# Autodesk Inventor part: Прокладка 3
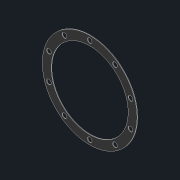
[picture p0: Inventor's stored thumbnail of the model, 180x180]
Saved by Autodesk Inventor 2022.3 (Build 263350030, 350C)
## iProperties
Created: 2022-08
Part Number: Прокладка 3
Material: Резина
Document SubType Name: Modeling
Designer: Карташов
Density: 0.93 g/cm^3
Appearance: Резина — черная
Author: Карташов
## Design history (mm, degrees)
sketch "Эскиз1"
  geometry: L1 (-320, -7.5)-(-320, 7.5) reference; L2 (-320, -7.5)-(-208, -7.5) reference; L3 (-68, -7.5)-(-25, -7.5) reference; L4 (105, -7.5)-(145, -7.5) reference; L5 (235, -7.5)-(320, -7.5) reference; L6 (320, 7.5)-(320, -7.5) reference; L7 (320, 7.5)-(248.095, 7.5) reference; L8 (195, 52.291)-(195, 82.5) reference; L9 (185, 82.5)-(195, 82.5) reference; L10 (185, 82.5)-(185, 52.291) reference; L11 (131.905, 7.5)-(118.581, 7.5) reference; L12 (70, 66.662)-(70, 77.5) reference; L13 (60, 77.5)-(70, 77.5) reference; L14 (60, 77.5)-(60, 69.96) reference; L15 (20, 69.96)-(20, 77.5) reference; L16 (10, 77.5)-(20, 77.5) reference; L17 (10, 77.5)-(10, 66.662) reference; L18 (-38.581, 7.5)-(-54.334, 7.5) reference; L19 (-108, 72.03)-(-108, 82.5) reference; L20 (-118, 82.5)-(-108, 82.5) reference; L21 (-118, 82.5)-(-118, 75.114) reference; L22 (-158, 75.114)-(-158, 82.5) reference; L23 (-168, 82.5)-(-158, 82.5) reference; L24 (-168, 82.5)-(-168, 72.03) reference; L25 (-221.666, 7.5)-(-320, 7.5) reference; L26 (-208, -7.5)-(-320, -7.5) reference; L27 (-320, -7.5)-(-320, -22.5) reference; L28 (-320, -22.5)-(-305, -22.5) reference; L29 (-300, -27.5)-(-300, -187.5) reference; L30 (-300, -187.5)-(-285, -187.5) reference; L31 (-285, -27.5)-(-285, -187.5) reference; L32 (-221.666, -22.5)-(-280, -22.5) reference; L33 (-38.581, -22.5)-(-54.334, -22.5) reference; L34 (131.905, -22.5)-(118.581, -22.5) reference; L35 (280, -22.5)-(248.095, -22.5) reference; L36 (285, -187.5)-(285, -27.5) reference; L37 (285, -187.5)-(300, -187.5) reference; L38 (300, -187.5)-(300, -27.5) reference; L39 (320, -22.5)-(305, -22.5) reference; L40 (320, -22.5)-(320, -7.5) reference; L41 (320, -7.5)-(235, -7.5) reference; L42 (145, -7.5)-(105, -7.5) reference; L43 (-25, -7.5)-(-68, -7.5) reference; C1 r 4 at (-138, 70) reference; C2 r 4 at (-2.614, 51.154) reference; C3 r 4 at (144.534, 18.75) reference; C4 r 4 at (190, 45) reference; C5 r 4 at (40, 65) reference; C6 r 4 at (-92.447, 55.199) reference; C7 r 4 at (-183.553, 55.199) reference; C8 r 4 at (-28.952, 14.904) reference; C9 r 4 at (108.952, 14.904) reference; C10 r 4 at (235.466, 18.75) reference; C11 r 4 at (82.614, 51.154) reference; C12 r 4 at (-64.293, 16.449) reference; C13 r 4 at (-211.707, 16.449) reference; C14 r 4 at (144.534, -33.75) reference; C15 r 4 at (235.466, -33.75) reference; C16 r 4 at (190, -60) reference; C17 r 4 at (82.614, -66.154) reference; C18 r 4 at (108.952, -29.904) reference; C19 r 4 at (-28.952, -29.904) reference; C20 r 4 at (-2.614, -66.154) reference; C21 r 4 at (40, -80) reference; C22 r 4 at (-92.447, -70.199) reference; C23 r 4 at (-64.293, -31.449) reference; C24 r 4 at (-211.707, -31.449) reference; C25 r 4 at (-183.553, -70.199) reference; C26 r 4 at (-138, -85) reference; C27 r 80 at (40, -7.5); A1 r 70 centre (-138, -7.5) between (-68, -7.5) and (-208, -7.5) reference; A2 r 65 centre (40, -7.5) between (105, -7.5) and (-25, -7.5) reference; A3 r 45 centre (190, -7.5) between (235, -7.5) and (145, -7.5) reference; A4 r 60 centre (190, -7.5) between (248.095, 7.5) and (195, 52.291) reference; A5 r 60 centre (190, -7.5) between (185, 52.291) and (131.905, 7.5) reference; A6 r 80 centre (40, -7.5) between (118.581, 7.5) and (70, 66.662) reference; A7 r 80 centre (40, -7.5) between (60, 69.96) and (20, 69.96) reference; A8 r 80 centre (40, -7.5) between (10, 66.662) and (-38.581, 7.5) reference; A9 r 85 centre (-138, -7.5) between (-54.334, 7.5) and (-108, 72.03) reference; A10 r 85 centre (-138, -7.5) between (-118, 75.114) and (-158, 75.114) reference; A11 r 85 centre (-138, -7.5) between (-168, 72.03) and (-221.666, 7.5) reference; A12 r 5 centre (-305, -27.5) between (-300, -27.5) and (-305, -22.5) reference; A13 r 5 centre (-280, -27.5) between (-280, -22.5) and (-285, -27.5) reference; A14 r 85 centre (-138, -7.5) between (-221.666, -22.5) and (-168, -87.03) reference; A15 r 85 centre (-138, -7.5) between (-168, -87.03) and (-158, -90.114) reference; A16 r 85 centre (-138, -7.5) between (-158, -90.114) and (-118, -90.114) reference; A17 r 85 centre (-138, -7.5) between (-118, -90.114) and (-108, -87.03) reference; A18 r 85 centre (-138, -7.5) between (-108, -87.03) and (-54.334, -22.5) reference; A19 r 80 centre (40, -7.5) between (-38.581, -22.5) and (10, -81.662) reference; A20 r 80 centre (40, -7.5) between (10, -81.662) and (20, -84.96) reference; A21 r 80 centre (40, -7.5) between (20, -84.96) and (60, -84.96) reference; A22 r 80 centre (40, -7.5) between (60, -84.96) and (70, -81.662) reference; A23 r 80 centre (40, -7.5) between (70, -81.662) and (118.581, -22.5) reference; A24 r 60 centre (190, -7.5) between (131.905, -22.5) and (160, -59.462) reference; A25 r 60 centre (190, -7.5) between (160, -59.462) and (170, -64.069) reference; A26 r 60 centre (190, -7.5) between (170, -64.069) and (210, -64.069) reference; A27 r 60 centre (190, -7.5) between (210, -64.069) and (220, -59.462) reference; A28 r 60 centre (190, -7.5) between (220, -59.462) and (248.095, -22.5) reference; A29 r 5 centre (280, -27.5) between (285, -27.5) and (280, -22.5) reference; A30 r 5 centre (305, -27.5) between (305, -22.5) and (300, -27.5) reference; A31 r 45 centre (190, -7.5) between (145, -7.5) and (235, -7.5) reference; A32 r 65 centre (40, -7.5) between (-25, -7.5) and (105, -7.5) reference; A33 r 70 centre (-138, -7.5) between (-208, -7.5) and (-68, -7.5) reference; 9 further points
  constraints: 1 centre point, 1 coincident, 1 concentric
extrude "Выдавливание1" new body sketch "Эскиз1" distance "d0" = 1; taper "d1" = 0 deg
node "Твердое тело1"
node "Ссылка1"
node "Ссылка2"
